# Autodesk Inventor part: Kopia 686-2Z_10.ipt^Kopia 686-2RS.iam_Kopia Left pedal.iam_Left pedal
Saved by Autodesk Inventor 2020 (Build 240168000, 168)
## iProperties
Created: 2017-10
Part Number: Kopia 686-2Z_10.ipt^Kopia 686-2RS.iam_Kopia Left pedal.iam_Left pedal
Material: Ogólny
Document SubType Name: Modeling
Designer: Tomasz
Density: 1 g/cm^3
Appearance: Domyślna
Sending System: SolidWorks 2017
Last Author: Tomasz
Last Saved: 2017-10-01
Author: Tomasz
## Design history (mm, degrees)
